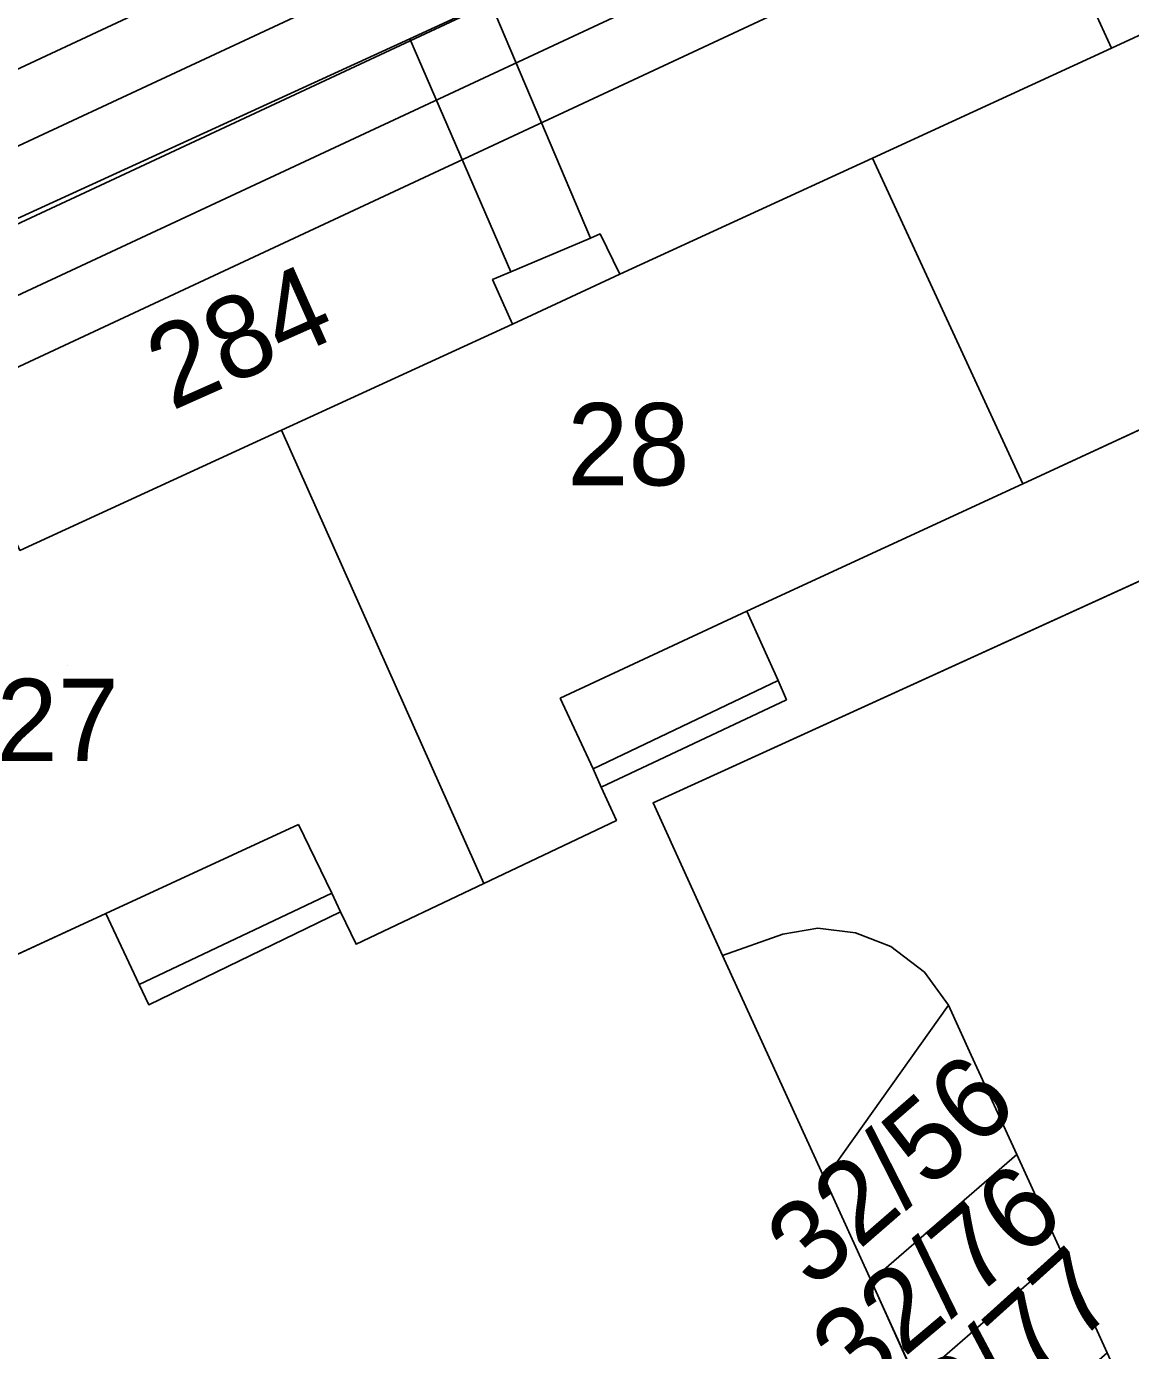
# Model space of a CAD drawing. Extents: x -264070 to -262271, y -1238894 to -1238141.
# Drawn here: x -263503.54 to -263476.71, y -1238728.04 to -1238695.87 of the extents above; entities that cross this region are included whole.
import ezdxf

# ---------------------------------------------------------------- set-up
doc = ezdxf.new("R2010")
doc.units = 0
for name, color, linetype in [('body_kn', 7, 'Continuous'), ('kladpar_druhypozemkov', 7, 'Continuous'), ('kladpar_hranice', 7, 'Continuous'), ('kladpar_parcelnecisla', 7, 'Continuous'), ('kladpar_plochy', 7, 'Continuous'), ('tarchy_linie', 7, 'Continuous'), ('zappar_hrandruhpozemk', 7, 'Continuous')]:
    doc.layers.add(name, color=color, linetype=linetype)

msp = doc.modelspace()

# ---------------------------------------------------------------- linework, layer by layer
at = {"layer": 'body_kn'}
for p, q in [((-263494.22, -1238696.17), (-263494.22, -1238696.17)), ((-263494.22, -1238696.17), (-263494.22, -1238696.17)), ((-263477.17, -1238696.4), (-263477.17, -1238696.4)), ((-263477.17, -1238696.4), (-263477.17, -1238696.4)), ((-263482.98, -1238699.07), (-263482.98, -1238699.07)), ((-263489.83, -1238701.01), (-263489.83, -1238701.01)), ((-263489.6, -1238700.91), (-263489.6, -1238700.91)), ((-263491.77, -1238701.83), (-263491.77, -1238701.83)), ((-263489.12, -1238701.89), (-263489.12, -1238701.89)), ((-263492.21, -1238702.02), (-263492.21, -1238702.02)), ((-263491.73, -1238703.1), (-263491.73, -1238703.1)), ((-263491.73, -1238703.1), (-263491.73, -1238703.1)), ((-263497.34, -1238705.68), (-263497.34, -1238705.68)), ((-263497.34, -1238705.68), (-263497.34, -1238705.68)), ((-263479.32, -1238706.98), (-263479.32, -1238706.98)), ((-263486.03, -1238710.08), (-263486.03, -1238710.08)), ((-263485.27, -1238711.76), (-263485.27, -1238711.76)), ((-263485.27, -1238711.76), (-263485.27, -1238711.76)), ((-263490.57, -1238712.19), (-263490.57, -1238712.19)), ((-263485.07, -1238712.23), (-263485.07, -1238712.23)), ((-263485.07, -1238712.23), (-263485.07, -1238712.23)), ((-263489.77, -1238713.91), (-263489.77, -1238713.91)), ((-263489.57, -1238714.35), (-263489.57, -1238714.35)), ((-263489.57, -1238714.35), (-263489.57, -1238714.35)), ((-263488.31, -1238714.73), (-263488.31, -1238714.73)), ((-263488.31, -1238714.73), (-263488.31, -1238714.73)), ((-263489.2, -1238715.16), (-263489.2, -1238715.16)), ((-263496.93, -1238715.26), (-263496.93, -1238715.26)), ((-263492.42, -1238716.69), (-263492.42, -1238716.69)), ((-263496.12, -1238716.93), (-263496.12, -1238716.93)), ((-263496.12, -1238716.93), (-263496.12, -1238716.93)), ((-263501.61, -1238717.42), (-263501.61, -1238717.42)), ((-263501.61, -1238717.42), (-263501.61, -1238717.42)), ((-263495.91, -1238717.38), (-263495.91, -1238717.38)), ((-263485.16, -1238717.92), (-263485.16, -1238717.92)), ((-263484.31, -1238717.78), (-263484.31, -1238717.78)), ((-263483.39, -1238717.89), (-263483.39, -1238717.89)), ((-263495.53, -1238718.17), (-263495.53, -1238718.17)), ((-263482.53, -1238718.22), (-263482.53, -1238718.22)), ((-263486.62, -1238718.44), (-263486.62, -1238718.44)), ((-263486.62, -1238718.44), (-263486.62, -1238718.44)), ((-263481.71, -1238718.85), (-263481.71, -1238718.85)), ((-263500.8, -1238719.15), (-263500.8, -1238719.15)), ((-263500.57, -1238719.64), (-263500.57, -1238719.64)), ((-263481.13, -1238719.65), (-263481.13, -1238719.65)), ((-263480.58, -1238720.86), (-263480.58, -1238720.86)), ((-263479.47, -1238723.28), (-263479.47, -1238723.28)), ((-263484.14, -1238723.88), (-263484.14, -1238723.88)), ((-263484.14, -1238723.88), (-263484.14, -1238723.88)), ((-263478.37, -1238725.69), (-263478.37, -1238725.69)), ((-263483.01, -1238726.35), (-263483.01, -1238726.35)), ((-263483.01, -1238726.35), (-263483.01, -1238726.35))]:
    msp.add_line(p, q, dxfattribs=at)
at = {"layer": 'kladpar_druhypozemkov'}
for p, q in [((-263498.83, -1238702.39), (-263498.83, -1238702.39)), ((-263488.23, -1238704.96), (-263488.23, -1238704.96)), ((-263502.55, -1238711.4), (-263502.55, -1238711.4)), ((-263482.23, -1238723.06), (-263482.23, -1238723.06)), ((-263481.14, -1238726.48), (-263481.14, -1238726.48))]:
    msp.add_line(p, q, dxfattribs=at)
at = {"layer": 'kladpar_hranice'}
msp.add_line((-263489.57, -1238714.35), (-263485.07, -1238712.23), dxfattribs=at)
for points in [[(-263500.65, -1238688.35), (-263451.62, -1238665.5), (-263451.29, -1238664.22), (-263451.05, -1238663.23), (-263451.17, -1238661.43), (-263451.46, -1238659.87), (-263450.51, -1238661.82), (-263443.95, -1238676.52), (-263443.28, -1238678.18), (-263444.69, -1238676.08), (-263445.94, -1238674.82), (-263447.38, -1238674.33), (-263461.74, -1238681.05), (-263463.63, -1238681.93), (-263477.86, -1238688.59), (-263479.69, -1238689.45), (-263486.41, -1238692.59), (-263492.27, -1238695.27), (-263494.22, -1238696.17), (-263506.95, -1238701.99)], [(-263477.17, -1238696.4), (-263477.7, -1238695.23), (-263477.17, -1238694.99), (-263475.33, -1238694.17), (-263474.95, -1238694), (-263474.42, -1238695.12), (-263468.77, -1238692.52), (-263465.17, -1238698.66), (-263464.35, -1238700.05), (-263470.57, -1238702.92), (-263469.35, -1238705.68), (-263469.73, -1238705.87), (-263471.23, -1238706.61), (-263471.6, -1238706.79), (-263472.88, -1238704), (-263479.32, -1238706.98), (-263482.98, -1238699.07), (-263477.17, -1238696.4)], [(-263477.7, -1238695.23), (-263477.17, -1238696.4), (-263482.98, -1238699.07), (-263489.12, -1238701.89), (-263489.6, -1238700.91), (-263489.83, -1238701.01), (-263491.77, -1238701.83), (-263492.21, -1238702.02), (-263491.73, -1238703.1), (-263497.34, -1238705.68), (-263503.7, -1238708.6)], [(-263494.22, -1238696.17), (-263492.27, -1238695.27)], [(-263506.95, -1238701.99), (-263494.22, -1238696.17)], [(-263485.07, -1238712.23), (-263485.27, -1238711.76), (-263486.03, -1238710.08), (-263479.32, -1238706.98), (-263472.88, -1238704), (-263471.6, -1238706.79), (-263471.23, -1238706.61), (-263469.73, -1238705.87), (-263469.35, -1238705.68), (-263470.57, -1238702.92), (-263464.35, -1238700.05), (-263465.17, -1238698.66), (-263460.98, -1238696.75), (-263458.86, -1238701.31), (-263488.31, -1238714.73), (-263486.62, -1238718.44), (-263484.14, -1238723.88), (-263483.01, -1238726.35), (-263481.91, -1238728.77)], [(-263491.73, -1238703.1), (-263492.21, -1238702.02), (-263491.77, -1238701.83), (-263489.83, -1238701.01), (-263489.6, -1238700.91), (-263489.12, -1238701.89), (-263482.98, -1238699.07), (-263479.32, -1238706.98), (-263486.03, -1238710.08), (-263485.27, -1238711.76), (-263485.07, -1238712.23), (-263489.57, -1238714.35), (-263489.2, -1238715.16), (-263492.42, -1238716.69), (-263497.34, -1238705.68), (-263491.73, -1238703.1)], [(-263488.31, -1238714.73), (-263458.86, -1238701.31), (-263457.28, -1238700.64), (-263455.89, -1238703.54), (-263452.36, -1238709.81), (-263460.03, -1238713.43), (-263459.39, -1238713.65), (-263458.52, -1238714.06), (-263457.7, -1238714.66), (-263457.03, -1238715.4), (-263456.43, -1238716.43), (-263454.35, -1238721.1), (-263446.66, -1238738.37), (-263445.55, -1238740.87), (-263436.66, -1238760.85), (-263440.11, -1238762.46), (-263449.26, -1238742.47), (-263450.41, -1238739.95), (-263459.57, -1238719.93), (-263471.24, -1238725.12)], [(-263497.34, -1238705.68), (-263492.42, -1238716.69), (-263495.53, -1238718.17), (-263495.91, -1238717.38), (-263500.57, -1238719.64), (-263500.8, -1238719.15), (-263501.61, -1238717.42), (-263508.28, -1238720.5), (-263512.18, -1238712.51), (-263506.11, -1238709.72), (-263506.53, -1238708.91), (-263506.08, -1238708.72), (-263504.32, -1238707.95), (-263504.04, -1238707.83), (-263503.7, -1238708.6), (-263497.34, -1238705.68)], [(-263508.28, -1238720.5), (-263501.61, -1238717.42), (-263500.8, -1238719.15), (-263500.57, -1238719.64), (-263495.91, -1238717.38), (-263495.53, -1238718.17), (-263492.42, -1238716.69), (-263489.2, -1238715.16), (-263489.57, -1238714.35)], [(-263473.74, -1238746.66), (-263474.99, -1238743.92), (-263470.9, -1238742.02), (-263471.44, -1238740.83), (-263472.86, -1238737.75), (-263473.96, -1238735.33), (-263475.06, -1238732.92), (-263476.17, -1238730.51), (-263477.27, -1238728.1), (-263478.37, -1238725.69), (-263479.47, -1238723.28), (-263480.58, -1238720.86), (-263481.13, -1238719.65), (-263484.14, -1238723.88), (-263486.62, -1238718.44), (-263488.31, -1238714.73)], [(-263484.14, -1238723.88), (-263481.13, -1238719.65), (-263480.58, -1238720.86), (-263479.47, -1238723.28), (-263483.01, -1238726.35), (-263484.14, -1238723.88)], [(-263483.01, -1238726.35), (-263479.47, -1238723.28), (-263478.37, -1238725.69), (-263481.91, -1238728.77), (-263483.01, -1238726.35)], [(-263480.81, -1238731.18), (-263481.91, -1238728.77), (-263478.37, -1238725.69), (-263477.27, -1238728.1), (-263480.81, -1238731.18)]]:
    msp.add_lwpolyline(points, dxfattribs=at)
at = {"layer": 'kladpar_plochy'}
for p, q in [((-263488.31, -1238714.73), (-263458.86, -1238701.31)), ((-263458.86, -1238701.31), (-263488.31, -1238714.73)), ((-263479.32, -1238706.98), (-263472.88, -1238704)), ((-263486.03, -1238710.08), (-263479.32, -1238706.98)), ((-263485.27, -1238711.76), (-263486.03, -1238710.08)), ((-263485.07, -1238712.23), (-263485.27, -1238711.76)), ((-263489.57, -1238714.35), (-263485.07, -1238712.23)), ((-263489.2, -1238715.16), (-263489.57, -1238714.35)), ((-263486.62, -1238718.44), (-263488.31, -1238714.73)), ((-263488.31, -1238714.73), (-263486.62, -1238718.44)), ((-263492.42, -1238716.69), (-263489.2, -1238715.16)), ((-263495.53, -1238718.17), (-263492.42, -1238716.69)), ((-263508.28, -1238720.5), (-263501.61, -1238717.42)), ((-263501.61, -1238717.42), (-263500.8, -1238719.15)), ((-263500.57, -1238719.64), (-263495.91, -1238717.38)), ((-263495.91, -1238717.38), (-263495.53, -1238718.17)), ((-263484.14, -1238723.88), (-263486.62, -1238718.44)), ((-263486.62, -1238718.44), (-263484.14, -1238723.88)), ((-263500.8, -1238719.15), (-263500.57, -1238719.64)), ((-263481.13, -1238719.65), (-263484.14, -1238723.88)), ((-263480.58, -1238720.86), (-263481.13, -1238719.65)), ((-263479.47, -1238723.28), (-263480.58, -1238720.86)), ((-263478.37, -1238725.69), (-263479.47, -1238723.28)), ((-263484.14, -1238723.88), (-263483.01, -1238726.35)), ((-263477.27, -1238728.1), (-263478.37, -1238725.69)), ((-263483.01, -1238726.35), (-263481.91, -1238728.77))]:
    msp.add_line(p, q, dxfattribs=at)
for points in [[(-263558.88, -1238715.6), (-263500.65, -1238688.35), (-263451.62, -1238665.5), (-263451.29, -1238664.22), (-263451.05, -1238663.23), (-263451.17, -1238661.43), (-263451.46, -1238659.87), (-263450.51, -1238661.82), (-263443.95, -1238676.52), (-263443.28, -1238678.18), (-263444.69, -1238676.08), (-263445.94, -1238674.82), (-263447.38, -1238674.33), (-263461.74, -1238681.05), (-263463.63, -1238681.93), (-263477.86, -1238688.59), (-263479.69, -1238689.45), (-263486.41, -1238692.59), (-263492.27, -1238695.27), (-263494.22, -1238696.17), (-263506.95, -1238701.99)], [(-263477.7, -1238695.23), (-263477.17, -1238696.4), (-263482.98, -1238699.07), (-263489.12, -1238701.89), (-263489.6, -1238700.91), (-263489.83, -1238701.01), (-263491.77, -1238701.83), (-263492.21, -1238702.02), (-263491.73, -1238703.1), (-263497.34, -1238705.68), (-263503.7, -1238708.6)], [(-263506.95, -1238701.99), (-263494.22, -1238696.17), (-263492.27, -1238695.27)]]:
    msp.add_lwpolyline(points, dxfattribs=at)
for points in [[(-263477.17, -1238696.4), (-263477.7, -1238695.23), (-263477.17, -1238694.99), (-263475.33, -1238694.17), (-263474.95, -1238694), (-263474.42, -1238695.12), (-263468.77, -1238692.52), (-263465.17, -1238698.66), (-263464.35, -1238700.05), (-263470.57, -1238702.92), (-263469.35, -1238705.68), (-263469.73, -1238705.87), (-263471.23, -1238706.61), (-263471.6, -1238706.79), (-263472.88, -1238704), (-263479.32, -1238706.98), (-263482.98, -1238699.07)], [(-263491.73, -1238703.1), (-263492.21, -1238702.02), (-263491.77, -1238701.83), (-263489.83, -1238701.01), (-263489.6, -1238700.91), (-263489.12, -1238701.89), (-263482.98, -1238699.07), (-263479.32, -1238706.98), (-263486.03, -1238710.08), (-263485.27, -1238711.76), (-263485.07, -1238712.23), (-263489.57, -1238714.35), (-263489.2, -1238715.16), (-263492.42, -1238716.69), (-263497.34, -1238705.68)], [(-263497.34, -1238705.68), (-263492.42, -1238716.69), (-263495.53, -1238718.17), (-263495.91, -1238717.38), (-263500.57, -1238719.64), (-263500.8, -1238719.15), (-263501.61, -1238717.42), (-263508.28, -1238720.5), (-263512.18, -1238712.51), (-263506.11, -1238709.72), (-263506.53, -1238708.91), (-263506.08, -1238708.72), (-263504.32, -1238707.95), (-263504.04, -1238707.83), (-263503.7, -1238708.6)], [(-263484.14, -1238723.88), (-263481.13, -1238719.65), (-263480.58, -1238720.86), (-263479.47, -1238723.28), (-263483.01, -1238726.35)], [(-263483.01, -1238726.35), (-263479.47, -1238723.28), (-263478.37, -1238725.69), (-263481.91, -1238728.77)], [(-263480.81, -1238731.18), (-263481.91, -1238728.77), (-263478.37, -1238725.69), (-263477.27, -1238728.1)]]:
    msp.add_lwpolyline(points, close=True, dxfattribs=at)
at = {"layer": 'tarchy_linie'}
msp.add_line((-263453.43, -1238678.93), (-263558.58, -1238727.98), dxfattribs=at)
for points in [[(-263333.22, -1238626.09), (-263444.51, -1238675.68), (-263431.45, -1238704.34), (-263432.86, -1238704.96), (-263434.27, -1238705.57), (-263447.24, -1238677.1), (-263448.92, -1238678.09), (-263435.73, -1238706.21), (-263438.67, -1238707.5), (-263441.6, -1238708.78), (-263454.53, -1238681.18), (-263557.89, -1238729.4)], [(-263559.26, -1238726.56), (-263456.12, -1238678.44), (-263458.17, -1238675.49), (-263479.68, -1238685.66), (-263520.43, -1238704.69)]]:
    msp.add_lwpolyline(points, dxfattribs=at)
at = {"layer": 'zappar_hrandruhpozemk'}
for p, q in [((-263477.17, -1238696.4), (-263474.42, -1238695.12)), ((-263492.27, -1238695.27), (-263489.83, -1238701.01)), ((-263494.22, -1238696.17), (-263491.77, -1238701.83)), ((-263491.73, -1238703.1), (-263489.12, -1238701.89)), ((-263490.57, -1238712.19), (-263486.03, -1238710.08)), ((-263485.27, -1238711.76), (-263489.77, -1238713.91)), ((-263501.61, -1238717.42), (-263496.93, -1238715.26)), ((-263496.12, -1238716.93), (-263500.8, -1238719.15)), ((-263486.62, -1238718.44), (-263485.16, -1238717.92)), ((-263485.16, -1238717.92), (-263484.31, -1238717.78))]:
    msp.add_line(p, q, dxfattribs=at)
for points in [[(-263556.13, -1238723.09), (-263505.88, -1238699.77), (-263451.6, -1238674.47)], [(-263489.57, -1238714.35), (-263489.77, -1238713.91), (-263490.57, -1238712.19)], [(-263496.93, -1238715.26), (-263496.12, -1238716.93), (-263495.91, -1238717.38)], [(-263484.31, -1238717.78), (-263483.39, -1238717.89), (-263482.53, -1238718.22), (-263481.71, -1238718.85), (-263481.13, -1238719.65)]]:
    msp.add_lwpolyline(points, dxfattribs=at)

# ---------------------------------------------------------------- texts
at = {"layer": 'kladpar_parcelnecisla'}
for s, rotation, p in [('284', 24, (-263500.011, -1238705.217)), ('32/56', 41, (-263484.427, -1238726.585)), ('32/76', 40, (-263483.36, -1238729.183)), ('32/77', 42, (-263481.863, -1238731.359))]:
    msp.add_text(s, height=2, rotation=rotation, dxfattribs=at).set_placement(p)
for s, p in [('28', (-263490.398, -1238707.02)), ('27', (-263504.267, -1238713.72))]:
    msp.add_text(s, height=2, dxfattribs=at).set_placement(p)

doc.saveas('drawing.dxf')
